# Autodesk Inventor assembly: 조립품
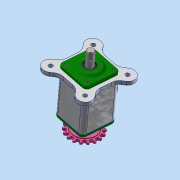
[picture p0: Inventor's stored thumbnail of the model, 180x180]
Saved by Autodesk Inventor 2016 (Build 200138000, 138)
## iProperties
Created: 2019-11
Part Number: 조립품
Material: 일반
Document SubType Name: Assembly
Designer: user
Author: user
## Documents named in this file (11)
- C:\Users\user\Desktop\491109V1010\조립품.iam
- C:\Users\user\Desktop\491109V1010\베어링 6203.ipt
- C:\Users\user\Desktop\491109V1010\본체.ipt
- C:\Users\user\Desktop\491109V1010\볼트 M4.ipt
- C:\Users\user\Desktop\491109V1010\부시.ipt
- C:\Users\user\Desktop\491109V1010\스프로킷.ipt
- C:\Users\user\Desktop\491109V1010\슬라이더.ipt
- C:\Users\user\Desktop\491109V1010\오일 실.ipt
- C:\Users\user\Desktop\491109V1010\커버.ipt
- C:\Users\user\Desktop\491109V1010\키 4 x 4 x 14.ipt
- C:\Users\user\Desktop\491109V1010\편심축.ipt
